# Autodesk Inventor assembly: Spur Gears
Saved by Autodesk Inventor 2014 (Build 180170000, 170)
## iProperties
Created: 2015-07
Part Number: Spur Gears
Document SubType Name: Assembly
Designer: Brad Factor
Categories: <?xml version="1.0" encoding="UTF-16"?> <MemberInstance><Categories><FamilyTemplate/><ParamToTemplateMap><ParamToTemplate><ParamToTemplate CategoryParameter="//
ClientObjectVersion: 1
Author: Brad Factor
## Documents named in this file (3)
- Z:\Projects\Graduate School\Courses\Haptics\HapKit\HapKit Gear Design\Design Accelerator\Spur Gears1.iam
- Z:\Projects\Graduate School\Courses\Haptics\HapKit\HapKit Gear Design\Design Accelerator\Spur Gear11.ipt
- Z:\Projects\Graduate School\Courses\Haptics\HapKit\HapKit Gear Design\Design Accelerator\Spur Gear21.ipt
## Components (2 placed, 2 different names)
1. Spur Gear1:1 — Rotation:1
2. Spur Gear2:1 — Rotation:1
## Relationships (1: RelateRotation 1)
- Rotation:1 [RelateRotation]: Spur Gear1:1 ↔ Spur Gear2:1
